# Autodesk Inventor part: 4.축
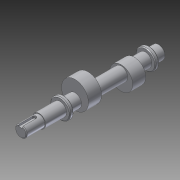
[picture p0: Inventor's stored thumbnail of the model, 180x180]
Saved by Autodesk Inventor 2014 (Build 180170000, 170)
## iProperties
Created: 2014-12
Part Number: 4.축
Material: 알루미늄 6061
Document SubType Name: Modeling
Designer: Owner
Mass: 170.354 g
Surface Area: 153.402 cm^2
Volume: 62.8614 cm^3
Density: 2.71 g/cm^3
Appearance: 알루미늄 - 평지
Author: Owner
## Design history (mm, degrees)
sketch "스케치1"
  geometry: L1 (0, 0)-(180, 0); L2 (0, 0)-(0, 7.5); L3 (0, 7.5)-(24, 7.5); L4 (24, 7.5)-(24, 8.5); L5 (24, 8.5)-(51, 8.5); L6 (51, 8.5)-(51, 13); L7 (51, 13)-(56, 13); L8 (56, 13)-(56, 8.5); L9 (56, 8.5)-(162, 8.5); L10 (162, 8.5)-(162, 13); L11 (162, 13)-(167, 13); L12 (167, 13)-(167, 8.5); L13 (167, 8.5)-(180, 8.5); L14 (180, 0)-(180, 8.5)
  constraints: 28 end point, 8 parallel, 5 perpendicular, 1 horizontal
  dimensions: "d0" = 180 distance of L1.start L1.end; "d1" = 15 diameter of L3 L1; "d2" = 17 diameter of L5 L1; "d3" = 26 diameter of L7 L1; "d4" = 26 diameter of L11 L1; "d5" = 24 distance of L2.end L3.end; "d6" = 27 distance of L4.end L5.end; "d7" = 5 distance of L6.end L7.end; "d8" = 5 distance of L10.end L11.end; "d9" = 13 distance of L12.end L13.end; "d10" = 17 diameter of L13 L1; "d11" = 17 diameter of L9 L1
revolve "회전1" sketch "스케치1" stored, may be unused: angle "d12" = 90 deg
node "작업 평면1"
sketch "스케치2"
  geometry: C1 r 17.5 at (0, 6); 1 further point
  constraints: 1 centre point, 1 vertical alignment
  dimensions: "d14" = 6 distance of point (0, 0) C1.centre; "d15" = 35 diameter of C1
extrude "돌출1" join sketch "스케치2" distance "d16" = 17; taper "d17" = 0 deg
node "작업 평면2"
sketch "스케치3"
  geometry: C1 r 15 at (0, -11); 1 further point
  constraints: 1 centre point, 1 vertical alignment
  dimensions: "d19" = 30 diameter of C1; "d20" = 5 distance of C1.centre point (0, -6)
extrude "돌출2" join sketch "스케치3" distance "d21" = 17; taper "d22" = 0 deg
node "작업 평면3"
sketch "스케치4"
  geometry: L1 (12, -2.5)-(-8, -2.5); L2 (-8, -2.5)-(-8, 2.5); L3 (-8, 2.5)-(12, 2.5); L4 (12, 2.5)-(12, -2.5); 3 further points
  constraints: 8 end point, 2 coincident, 2 midpoint, 2 parallel, 1 horizontal, 1 horizontal alignment, 1 perpendicular
  dimensions: "d23" = 20 distance of L1.start L1.end; "d24" = 5 distance of L3.end L1.start
extrude "돌출3" cut sketch "스케치4" distance "d25" = 3; taper "d26" = 0 deg
fillet "모깎기1" dims "d27" = 2.5
chamfer "모따기1" distance "d28" = 1; stored, may be unused: second distance "d29" = 2, angle "d30" = 45 deg
node "솔리드1"
other parameters: "d13" = -70.5, "d18" = 43
